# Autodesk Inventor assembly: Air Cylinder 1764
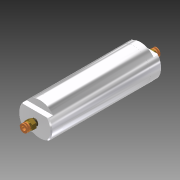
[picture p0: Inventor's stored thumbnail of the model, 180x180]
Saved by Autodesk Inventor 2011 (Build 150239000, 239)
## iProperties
Created: 2010-01
Part Number: Air Cylinder 1764
Document SubType Name: Assembly
Designer: cmcfadden
Author: cmcfadden
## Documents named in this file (4)
- R:\CAD Archives\Pneumatics\Air Cylinder 1764\Air Cylinder 1764.iam
- R:\CAD Archives\Pneumatics\Air Cylinder 1764\Air Cylinder Base 1764.ipt
- R:\CAD Archives\Pneumatics\Air Cylinder 1764\Air Cylinder End 1764.ipt
- R:\CAD Archives\Pneumatics\Air Cylinder 1764\Pnewmatic Screw 1764\Pneumatic Screw 1764.iam
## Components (5 placed, 3 different names)
1. Air Cylinder Base 1764:1 — Mate:1, Tangent:1, Mate:2, Tangent:2
2. Air Cylinder End 1764:1 — Mate:1, Tangent:1, Mate:4, Mate:6
3. Air Cylinder End 1764:2 — Mate:2, Tangent:2, Mate:3, Mate:5
4. Pneumatic Screw 1764:1 [sub-assembly] — Mate:3, Mate:5
5. Pneumatic Screw 1764:2 [sub-assembly] — Mate:4, Mate:6
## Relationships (8: Mate 6, Tangent 2)
- Mate:1: Air Cylinder Base 1764:1 ↔ Air Cylinder End 1764:1
- Tangent:1: Air Cylinder Base 1764:1 ↔ Air Cylinder End 1764:1
- Mate:2: Air Cylinder Base 1764:1 ↔ Air Cylinder End 1764:2
- Tangent:2: Air Cylinder Base 1764:1 ↔ Air Cylinder End 1764:2
- Mate:3: Air Cylinder End 1764:2 ↔ Pneumatic Screw 1764:1
- Mate:4: Air Cylinder End 1764:1 ↔ Pneumatic Screw 1764:2
- Mate:5: Air Cylinder End 1764:2 ↔ Pneumatic Screw 1764:1
- Mate:6: Air Cylinder End 1764:1 ↔ Pneumatic Screw 1764:2
